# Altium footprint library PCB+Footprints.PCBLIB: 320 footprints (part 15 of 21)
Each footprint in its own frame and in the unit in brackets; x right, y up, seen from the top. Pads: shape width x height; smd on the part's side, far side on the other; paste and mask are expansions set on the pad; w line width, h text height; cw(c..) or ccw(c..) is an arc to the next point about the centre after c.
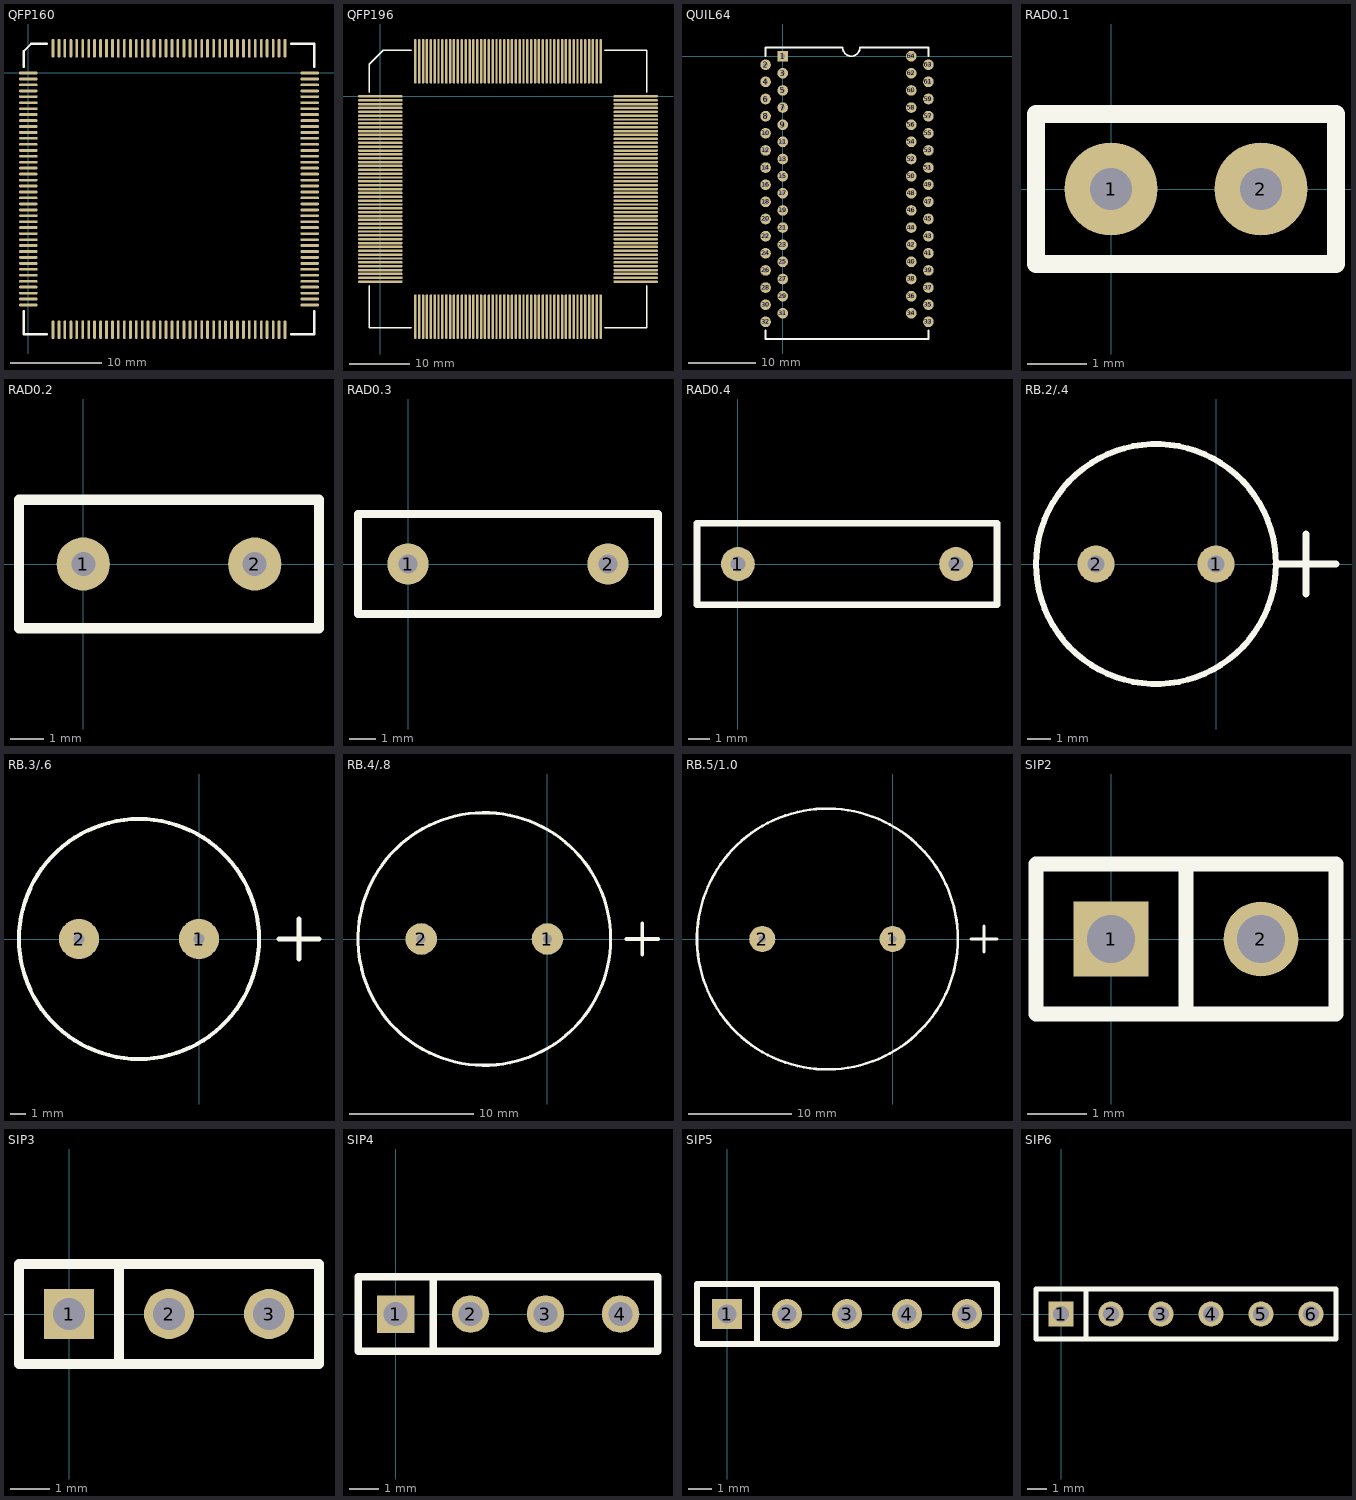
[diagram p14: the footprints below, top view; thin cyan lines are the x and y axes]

## QFP160 [mil]
pads (160):
  oval 80x12 smd: 1(0,0) 2(0,-26) 3(0,-51) 4(0,-77) 5(0,-102) 6(0,-128) 7(0,-154) 8(0,-179) 9(0,-205) 10(0,-230) 11(0,-256) 12(0,-281) 13(0,-307) 14(0,-333) 15(0,-358) 16(0,-384) 17(0,-409) 18(0,-435) 19(0,-461) 20(0,-486) 21(0,-512) 22(0,-537) 23(0,-563) 24(0,-589) 25(0,-614) 26(0,-640) 27(0,-665) 28(0,-691) 29(0,-717) 30(0,-742) 31(0,-768) 32(0,-793) 33(0,-819) 34(0,-844) 35(0,-870) 36(0,-896) 37(0,-921) 38(0,-947) 39(0,-972) 40(0,-998) 81(1210,-998) 82(1210,-972) 83(1210,-947) 84(1210,-921) 85(1210,-896) 86(1210,-870) 87(1210,-844) 88(1210,-819) 89(1210,-793) 90(1210,-768) 91(1210,-742) 92(1210,-717) 93(1210,-691) 94(1210,-665) 95(1210,-640) 96(1210,-614) 97(1210,-589) 98(1210,-563) 99(1210,-537) 100(1210,-512) 101(1210,-486) 102(1210,-461) 103(1210,-435) 104(1210,-409) 105(1210,-384) 106(1210,-358) 107(1210,-333) 108(1210,-307) 109(1210,-281) 110(1210,-256) 111(1210,-230) 112(1210,-205) 113(1210,-179) 114(1210,-154) 115(1210,-128) 116(1210,-102) 117(1210,-77) 118(1210,-51) 119(1210,-26) 120(1210,0)
  oval 12x80 smd: 41(106,-1104) 42(132,-1104) 43(157,-1104) 44(183,-1104) 45(208,-1104) 46(234,-1104) 47(260,-1104) 48(285,-1104) 49(311,-1104) 50(336,-1104) 51(362,-1104) 52(387,-1104) 53(413,-1104) 54(439,-1104) 55(464,-1104) 56(490,-1104) 57(515,-1104) 58(541,-1104) 59(567,-1104) 60(592,-1104) 61(618,-1104) 62(643,-1104) 63(669,-1104) 64(695,-1104) 65(720,-1104) 66(746,-1104) 67(771,-1104) 68(797,-1104) 69(823,-1104) 70(848,-1104) 71(874,-1104) 72(899,-1104) 73(925,-1104) 74(950,-1104) 75(976,-1104) 76(1002,-1104) 77(1027,-1104) 78(1053,-1104) 79(1078,-1104) 80(1104,-1104) 121(1104,106) 122(1078,106) 123(1053,106) 124(1027,106) 125(1002,106) 126(976,106) 127(950,106) 128(925,106) 129(899,106) 130(874,106) 131(848,106) 132(823,106) 133(797,106) 134(771,106) 135(746,106) 136(720,106) 137(695,106) 138(669,106) 139(643,106) 140(618,106) 141(592,106) 142(567,106) 143(541,106) 144(515,106) 145(490,106) 146(464,106) 147(439,106) 148(413,106) 149(387,106) 150(362,106) 151(336,106) 152(311,106) 153(285,106) 154(260,106) 155(234,106) 156(208,106) 157(183,106) 158(157,106) 159(132,106) 160(106,106)
TopOverlay:
  lines w10: -20,-1024 -20,-1124 80,-1124 ; -20,26 -20,93 13,126 80,126 ; 1130,-1124 1230,-1124 1230,-1024 ; 1130,126 1230,126 1230,26

## QFP196 [mil]
pads (196):
  oval 290x16 smd: 1(0,0) 2(0,-25) 3(0,-50) 4(0,-75) 5(0,-100) 6(0,-125) 7(0,-150) 8(0,-175) 9(0,-200) 10(0,-225) 11(0,-250) 12(0,-275) 13(0,-301) 14(0,-326) 15(0,-351) 16(0,-376) 17(0,-401) 18(0,-426) 19(0,-451) 20(0,-476) 21(0,-501) 22(0,-526) 23(0,-551) 24(0,-576) 25(0,-601) 26(0,-626) 27(0,-651) 28(0,-676) 29(0,-701) 30(0,-726) 31(0,-751) 32(0,-776) 33(0,-801) 34(0,-826) 35(0,-851) 36(0,-876) 37(0,-901) 38(0,-926) 39(0,-951) 40(0,-976) 41(0,-1001) 42(0,-1026) 43(0,-1051) 44(0,-1076) 45(0,-1101) 46(0,-1126) 47(0,-1151) 48(0,-1176) 49(0,-1201) 99(1655,-1201) 100(1655,-1176) 101(1655,-1151) 102(1655,-1126) 103(1655,-1101) 104(1655,-1076) 105(1655,-1051) 106(1655,-1026) 107(1655,-1001) 108(1655,-976) 109(1655,-951) 110(1655,-926) 111(1655,-901) 112(1655,-876) 113(1655,-851) 114(1655,-826) 115(1655,-801) 116(1655,-776) 117(1655,-751) 118(1655,-726) 119(1655,-701) 120(1655,-676) 121(1655,-651) 122(1655,-626) 123(1655,-601) 124(1655,-576) 125(1655,-551) 126(1655,-526) 127(1655,-501) 128(1655,-476) 129(1655,-451) 130(1655,-426) 131(1655,-401) 132(1655,-376) 133(1655,-351) 134(1655,-326) 135(1655,-301) 136(1655,-275) 137(1655,-250) 138(1655,-225) 139(1655,-200) 140(1655,-175) 141(1655,-150) 142(1655,-125) 143(1655,-100) 144(1655,-75) 145(1655,-50) 146(1655,-25) 147(1655,0)
  oval 16x290 smd: 50(227,-1428) 51(252,-1428) 52(277,-1428) 53(302,-1428) 54(327,-1428) 55(352,-1428) 56(377,-1428) 57(402,-1428) 58(427,-1428) 59(452,-1428) 60(477,-1428) 61(502,-1428) 62(528,-1428) 63(553,-1428) 64(578,-1428) 65(603,-1428) 66(628,-1428) 67(653,-1428) 68(678,-1428) 69(703,-1428) 70(728,-1428) 71(753,-1428) 72(778,-1428) 73(803,-1428) 74(828,-1428) 75(853,-1428) 76(878,-1428) 77(903,-1428) 78(928,-1428) 79(953,-1428) 80(978,-1428) 81(1003,-1428) 82(1028,-1428) 83(1053,-1428) 84(1078,-1428) 85(1103,-1428) 86(1128,-1428) 87(1153,-1428) 88(1178,-1428) 89(1203,-1428) 90(1228,-1428) 91(1253,-1428) 92(1278,-1428) 93(1303,-1428) 94(1328,-1428) 95(1353,-1428) 96(1378,-1428) 97(1403,-1428) 98(1428,-1428) 148(1428,227) 149(1403,227) 150(1378,227) 151(1353,227) 152(1328,227) 153(1303,227) 154(1278,227) 155(1253,227) 156(1228,227) 157(1203,227) 158(1178,227) 159(1153,227) 160(1128,227) 161(1103,227) 162(1078,227) 163(1053,227) 164(1028,227) 165(1003,227) 166(978,227) 167(953,227) 168(928,227) 169(903,227) 170(878,227) 171(853,227) 172(828,227) 173(803,227) 174(778,227) 175(753,227) 176(728,227) 177(703,227) 178(678,227) 179(653,227) 180(628,227) 181(603,227) 182(578,227) 183(553,227) 184(528,227) 185(502,227) 186(477,227) 187(452,227) 188(427,227) 189(402,227) 190(377,227) 191(352,227) 192(327,227) 193(302,227) 194(277,227) 195(252,227) 196(227,227)
TopOverlay:
  lines w10: -72,-1228 -72,-1500 200,-1500 ; -72,27 -72,209 18,299 200,299 ; 1455,-1500 1727,-1500 1727,-1228 ; 1455,299 1727,299 1727,27

## QUIL64 [mil]
pads (64):
  rect 62x62 hole 28: 1(0,0)
  round 62 hole 28: 2(-100,-50) 3(0,-100) 4(-100,-150) 5(0,-200) 6(-100,-250) 7(0,-300) 8(-100,-350) 9(0,-400) 10(-100,-450) 11(0,-500) 12(-100,-550) 13(0,-600) 14(-100,-650) 15(0,-700) 16(-100,-750) 17(0,-800) 18(-100,-850) 19(0,-900) 20(-100,-950) 21(0,-1000) 22(-100,-1050) 23(0,-1100) 24(-100,-1150) 25(0,-1200) 26(-100,-1250) 27(0,-1300) 28(-100,-1350) 29(0,-1400) 30(-100,-1450) 31(0,-1500) 32(-100,-1550) 33(850,-1550) 34(750,-1500) 35(850,-1450) 36(750,-1400) 37(850,-1350) 38(750,-1300) 39(850,-1250) 40(750,-1200) 41(850,-1150) 42(750,-1100) 43(850,-1050) 44(750,-1000) 45(850,-950) 46(750,-900) 47(850,-850) 48(750,-800) 49(850,-750) 50(750,-700) 51(850,-650) 52(750,-600) 53(850,-550) 54(750,-500) 55(850,-450) 56(750,-400) 57(850,-350) 58(750,-300) 59(850,-250) 60(750,-200) 61(850,-150) 62(750,-100) 63(850,-50) 64(750,0)
TopOverlay:
  lines w10: 350,50 ccw(c400,50) 450,50
  lines w12: -100,-1600 -100,-1650 850,-1650 850,-1600 ; -100,0 -100,50 350,50 ; 450,50 850,50 850,0

## RAD0.1 [mil]
pads (2):
  round 62 hole 28: 1(0,0) 2(100,0)
TopOverlay:
  lines w12: -50,-50 -50,50 150,50 150,-50 -50,-50

## RAD0.2 [mil]
pads (2):
  round 62 hole 28: 1(0,0) 2(200,0)
TopOverlay:
  lines w12: -75,-75 -75,75 275,75 275,-75 -75,-75

## RAD0.3 [mil]
pads (2):
  round 62 hole 28: 1(0,0) 2(300,0)
TopOverlay:
  lines w12: -75,-75 375,-75 375,75 -75,75 -75,-75

## RAD0.4 [mil]
pads (2):
  round 62 hole 28: 1(0,0) 2(400,0)
TopOverlay:
  lines w12: -75,-75 475,-75 475,75 -75,75 -75,-75

## RB.2/.4 [mil]
pads (2):
  round 62 hole 28: 1(0,0) 2(-200,0)
TopOverlay:
  circle w10: c-100,0 r200
  lines w12: 100,0 200,0 ; 150,-50 150,50

## RB.3/.6 [mil]
pads (2):
  round 100 hole 28: 1(0,0) 2(-300,0)
TopOverlay:
  circle w10: c-150,0 r300
  lines w12: 200,0 300,0 ; 250,-50 250,50

## RB.4/.8 [mil]
pads (2):
  round 100 hole 28: 1(0,0) 2(-400,0)
TopOverlay:
  circle w10: c-200,0 r400
  lines w12: 250,0 350,0 ; 300,-50 300,50

## RB.5/1.0 [mil]
pads (2):
  round 100 hole 28: 1(0,0) 2(-500,0)
TopOverlay:
  circle w10: c-250,0 r500
  lines w12: 300,0 400,0 ; 350,-50 350,50

## SIP2 [mil]
pads (2):
  rect 50x50 hole 32: 1(0,0)
  round 50 hole 32: 2(100,0)
TopOverlay:
  lines w10: 50,-50 50,50 ; -50,-50 150,-50 150,50 -50,50 -50,-50

## SIP3 [mil]
pads (3):
  rect 50x50 hole 32: 1(0,0)
  round 50 hole 32: 2(100,0) 3(200,0)
TopOverlay:
  lines w10: 50,-50 50,50 ; -50,-50 -50,50 250,50 250,-50 -50,-50

## SIP4 [mil]
pads (4):
  rect 50x50 hole 32: 1(0,0)
  round 50 hole 32: 2(100,0) 3(200,0) 4(300,0)
TopOverlay:
  lines w10: 50,-50 50,50 ; -50,-50 -50,50 350,50 350,-50 -50,-50

## SIP5 [mil]
pads (5):
  rect 50x50 hole 32: 1(0,0)
  round 50 hole 32: 2(100,0) 3(200,0) 4(300,0) 5(400,0)
TopOverlay:
  lines w10: 50,-50 50,50 ; -50,-50 -50,50 450,50 450,-50 -50,-50

## SIP6 [mil]
pads (6):
  rect 50x50 hole 32: 1(0,0)
  round 50 hole 32: 2(100,0) 3(200,0) 4(300,0) 5(400,0) 6(500,0)
TopOverlay:
  lines w10: 50,-50 50,50 ; -50,-50 550,-50 550,50 -50,50 -50,-50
